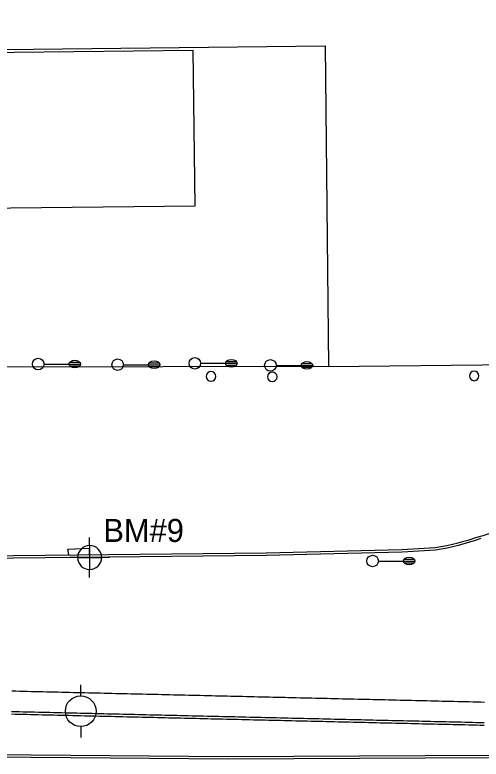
# Model space of a CAD drawing. Extents: x 2145380 to 2157287, y 139568 to 149130.
# Drawn here: x 2147980.9 to 2148102.2, y 143189.7 to 143383.4 of the extents above; entities that cross this region are included whole.
import ezdxf

# ---------------------------------------------------------------- set-up
doc = ezdxf.new("R2010")
doc.units = 0
for name, color, linetype in [('PR_PREVIOUSLY CONSTRUCTED', 7, 'Continuous'), ('SURV_Benchmark', 7, 'Continuous'), ('TOPO_Building', 7, 'Continuous'), ('TOPO_Curb Back', 7, 'Continuous'), ('TOPO_DRAIN_Inlet Grate', 7, 'Continuous'), ('TOPO_Fence', 7, 'Continuous'), ('TOPO_Light Pole', 7, 'Continuous'), ('TOPO_Misc', 7, 'Continuous'), ('TOPO_Misc Line', 7, 'Continuous'), ('TOPO_Power Pole', 7, 'Continuous')]:
    doc.layers.add(name, color=color, linetype=linetype)

# ---------------------------------------------------------------- blocks, each defined once
blk = doc.blocks.new('POST')
at = {"layer": 'TOPO_Misc'}
for start, end in [(90, 180), (180, 270), (360, 90), (270, 0)]:
    blk.add_arc((-0.01, 0.03), 3.16, start, end, dxfattribs=at)
blk = doc.blocks.new('LP')
at = {"layer": 'TOPO_Light Pole'}
blk.add_line((3.81, 0), (20.32, 0), dxfattribs=at)
for points in [[(20.32, 0), (27.94, 0)], [(20.32, 0), (23.5, 0)], [(20.83, 1.27), (27.43, 1.27)], [(20.83, 1.27), (23.5, 1.27)], [(23.71, 1.27), (27.43, 1.27)], [(23.71, 0), (27.94, 0)], [(20.83, -1.27), (27.43, -1.27)], [(20.83, -1.27), (23.5, -1.27)], [(23.71, -1.27), (27.43, -1.27)]]:
    blk.add_lwpolyline(points, dxfattribs=at)
blk.add_circle((0, 0), 3.81, dxfattribs=at)
blk.add_ellipse((24.13, 0), major_axis=(3.81, 0), ratio=0.666667, dxfattribs=at)
blk = doc.blocks.new('POWPOL')
at = {"layer": 'TOPO_Power Pole'}
for p, q in [((0, 10.16), (0, 17.34)), ((0, -10.16), (0, -17.34))]:
    blk.add_line(p, q, dxfattribs=at)
blk.add_circle((0, 0), 10.16, dxfattribs=at)
blk = doc.blocks.new('BM')
at = {"layer": 'SURV_Benchmark'}
for p, q in [((0, 2.49), (0, 4.15)), ((-2.49, 0), (-4.16, 0)), ((4.16, 0), (2.49, 0)), ((0, -4.16), (0, -2.49))]:
    blk.add_line(p, q, dxfattribs=at)
for points in [[(0, 2.49), (0, 2.49), (0, 0), (2.49, 0), (2.49, 0), (2.49, 0)], [(0, 2.49), (0, 2.49), (0, 0), (2.49, 0), (2.49, 0), (2.49, 0), (2.49, 0)], [(-2.5, 0), (-2.49, 0), (0, 0), (0, -2.49), (0, -2.49)], [(-2.5, 0), (-2.49, 0), (0, 0), (0, -2.49), (0, -2.49)]]:
    blk.add_lwpolyline(points, dxfattribs=at)
for start, end in [(90.0638, 180.0068), (0.0638, 90.0068), (0.0638, 90.0068), (180.0638, 270.0068), (180.0638, 270.0068), (269.9472, 359.9927)]:
    blk.add_arc((0, 0), 2.5, start, end, dxfattribs=at)

msp = doc.modelspace()

# ---------------------------------------------------------------- linework, layer by layer
at = {"layer": 'PR_PREVIOUSLY CONSTRUCTED'}
for points in [[(2147980.15, 143207.5), (2147981.15, 143207.48), (2147982.15, 143207.45), (2147983.15, 143207.43), (2147984.15, 143207.41), (2147985.15, 143207.38), (2147986.15, 143207.36), (2147987.15, 143207.34), (2147988.15, 143207.31), (2147989.15, 143207.29), (2147990.15, 143207.27), (2147991.15, 143207.24), (2147992.15, 143207.22), (2147993.15, 143207.19), (2147994.15, 143207.17), (2147995.15, 143207.15), (2147996.15, 143207.12), (2147997.15, 143207.1), (2147998.15, 143207.08), (2147999.15, 143207.05), (2148000.15, 143207.03), (2148001.15, 143207.01), (2148002.15, 143206.98), (2148003.15, 143206.96), (2148004.15, 143206.94), (2148005.15, 143206.91), (2148006.15, 143206.89), (2148007.15, 143206.86), (2148008.15, 143206.84), (2148009.15, 143206.82), (2148010.15, 143206.79), (2148011.15, 143206.77), (2148012.14, 143206.75), (2148013.14, 143206.72), (2148014.14, 143206.7), (2148015.14, 143206.68), (2148016.14, 143206.65), (2148017.14, 143206.63), (2148018.14, 143206.61), (2148019.14, 143206.58), (2148020.14, 143206.56), (2148021.14, 143206.54), (2148022.14, 143206.51), (2148023.14, 143206.49), (2148024.14, 143206.46), (2148025.14, 143206.44), (2148026.14, 143206.42), (2148027.14, 143206.39), (2148028.14, 143206.37), (2148029.14, 143206.35), (2148030.14, 143206.32), (2148031.14, 143206.3), (2148032.14, 143206.28), (2148033.14, 143206.25), (2148034.14, 143206.23), (2148035.14, 143206.2), (2148036.14, 143206.18), (2148037.14, 143206.16), (2148038.14, 143206.13), (2148039.14, 143206.11), (2148040.14, 143206.09), (2148041.14, 143206.06), (2148042.14, 143206.04), (2148043.14, 143206.02), (2148044.13, 143205.99), (2148045.13, 143205.97), (2148046.13, 143205.95), (2148047.13, 143205.92), (2148048.13, 143205.9), (2148049.13, 143205.88), (2148050.13, 143205.85), (2148051.13, 143205.83), (2148052.13, 143205.8), (2148053.13, 143205.78), (2148054.13, 143205.76), (2148055.13, 143205.73), (2148056.13, 143205.71), (2148057.13, 143205.69), (2148058.13, 143205.66), (2148059.13, 143205.64), (2148060.13, 143205.62), (2148061.13, 143205.59), (2148062.13, 143205.57), (2148063.13, 143205.55), (2148064.13, 143205.52), (2148065.13, 143205.5), (2148066.13, 143205.47), (2148067.13, 143205.45), (2148068.13, 143205.43), (2148069.13, 143205.4), (2148070.13, 143205.38), (2148071.13, 143205.36), (2148072.13, 143205.33), (2148073.13, 143205.31), (2148074.13, 143205.29), (2148075.13, 143205.26), (2148076.13, 143205.24), (2148077.13, 143205.22), (2148078.13, 143205.19), (2148079.13, 143205.17), (2148080.12, 143205.15), (2148081.12, 143205.12), (2148082.12, 143205.1), (2148083.12, 143205.07), (2148084.12, 143205.05), (2148085.12, 143205.03), (2148086.12, 143205), (2148087.12, 143204.98), (2148088.12, 143204.96), (2148089.12, 143204.93), (2148090.12, 143204.91), (2148091.12, 143204.89), (2148092.12, 143204.86), (2148093.12, 143204.84), (2148094.12, 143204.82), (2148095.12, 143204.79), (2148096.12, 143204.77), (2148097.12, 143204.74), (2148098.12, 143204.72), (2148099.12, 143204.7), (2148100.12, 143204.67), (2148101.12, 143204.65), (2148102.12, 143204.63), (2148103.12, 143204.6)], [(2147980.01, 143201.49), (2147981.01, 143201.47), (2147982.01, 143201.45), (2147983.01, 143201.42), (2147984.01, 143201.4), (2147985.01, 143201.38), (2147986.01, 143201.35), (2147987.01, 143201.33), (2147988.01, 143201.31), (2147989.01, 143201.28), (2147990.01, 143201.26), (2147991.01, 143201.24), (2147992.01, 143201.21), (2147993.01, 143201.19), (2147994.01, 143201.16), (2147995.01, 143201.14), (2147996.01, 143201.12), (2147997.01, 143201.09), (2147998.01, 143201.07), (2147999.01, 143201.05), (2148000.01, 143201.02), (2148001.01, 143201), (2148002.01, 143200.98), (2148003, 143200.95), (2148004, 143200.93), (2148005, 143200.91), (2148006, 143200.88), (2148007, 143200.86), (2148008, 143200.83), (2148009, 143200.81), (2148010, 143200.79), (2148011, 143200.77), (2148012, 143200.74), (2148013, 143200.72), (2148014, 143200.69), (2148015, 143200.67), (2148016, 143200.65), (2148017, 143200.62), (2148018, 143200.6), (2148019, 143200.58), (2148020, 143200.55), (2148021, 143200.53), (2148022, 143200.51), (2148023, 143200.48), (2148024, 143200.46), (2148025, 143200.43), (2148026, 143200.41), (2148027, 143200.39), (2148028, 143200.36), (2148029, 143200.34), (2148030, 143200.32), (2148031, 143200.29), (2148032, 143200.27), (2148033, 143200.25), (2148034, 143200.22), (2148035, 143200.2), (2148036, 143200.18), (2148037, 143200.15), (2148038, 143200.13), (2148038.99, 143200.1), (2148039.99, 143200.08), (2148040.99, 143200.06), (2148041.99, 143200.04), (2148042.99, 143200.01), (2148043.99, 143199.99), (2148044.99, 143199.96), (2148045.99, 143199.94), (2148046.99, 143199.92), (2148047.99, 143199.89), (2148048.99, 143199.87), (2148049.99, 143199.85), (2148050.99, 143199.82), (2148051.99, 143199.8), (2148052.99, 143199.78), (2148053.99, 143199.75), (2148054.99, 143199.73), (2148055.99, 143199.7), (2148056.99, 143199.68), (2148057.99, 143199.66), (2148058.99, 143199.63), (2148059.99, 143199.61), (2148060.99, 143199.59), (2148061.99, 143199.56), (2148062.99, 143199.54), (2148063.99, 143199.52), (2148064.99, 143199.49), (2148065.99, 143199.47), (2148066.99, 143199.45), (2148067.99, 143199.42), (2148068.99, 143199.4), (2148069.99, 143199.38), (2148070.99, 143199.35), (2148071.99, 143199.33), (2148072.99, 143199.3), (2148073.99, 143199.28), (2148074.98, 143199.26), (2148075.98, 143199.23), (2148076.98, 143199.21), (2148077.98, 143199.19), (2148078.98, 143199.16), (2148079.98, 143199.14), (2148080.98, 143199.12), (2148081.98, 143199.09), (2148082.98, 143199.07), (2148083.98, 143199.05), (2148084.98, 143199.02), (2148085.98, 143199), (2148086.98, 143198.97), (2148087.98, 143198.95), (2148088.98, 143198.93), (2148089.98, 143198.9), (2148090.98, 143198.88), (2148091.98, 143198.86), (2148092.98, 143198.83), (2148093.98, 143198.81), (2148094.98, 143198.79), (2148095.98, 143198.76), (2148096.98, 143198.74), (2148097.98, 143198.72), (2148098.98, 143198.69), (2148099.98, 143198.67), (2148100.98, 143198.64), (2148101.98, 143198.62), (2148102.98, 143198.6)], [(2147980.03, 143202.16), (2147981.03, 143202.14), (2147982.03, 143202.11), (2147983.03, 143202.09), (2147984.03, 143202.07), (2147985.03, 143202.04), (2147986.03, 143202.02), (2147987.02, 143202), (2147988.02, 143201.97), (2147989.02, 143201.95), (2147990.02, 143201.93), (2147991.02, 143201.9), (2147992.02, 143201.88), (2147993.02, 143201.86), (2147994.02, 143201.83), (2147995.02, 143201.81), (2147996.02, 143201.79), (2147997.02, 143201.76), (2147998.02, 143201.74), (2147999.02, 143201.71), (2148000.02, 143201.69), (2148001.02, 143201.67), (2148002.02, 143201.64), (2148003.02, 143201.62), (2148004.02, 143201.6), (2148005.02, 143201.57), (2148006.02, 143201.55), (2148007.02, 143201.53), (2148008.02, 143201.5), (2148009.02, 143201.48), (2148010.02, 143201.46), (2148011.02, 143201.43), (2148012.02, 143201.41), (2148013.02, 143201.38), (2148014.02, 143201.36), (2148015.02, 143201.34), (2148016.02, 143201.31), (2148017.02, 143201.29), (2148018.02, 143201.27), (2148019.02, 143201.24), (2148020.02, 143201.22), (2148021.02, 143201.2), (2148022.02, 143201.17), (2148023.01, 143201.15), (2148024.01, 143201.13), (2148025.01, 143201.1), (2148026.01, 143201.08), (2148027.01, 143201.05), (2148028.01, 143201.03), (2148029.01, 143201.01), (2148030.01, 143200.98), (2148031.01, 143200.96), (2148032.01, 143200.94), (2148033.01, 143200.91), (2148034.01, 143200.89), (2148035.01, 143200.87), (2148036.01, 143200.84), (2148037.01, 143200.82), (2148038.01, 143200.8), (2148039.01, 143200.77), (2148040.01, 143200.75), (2148041.01, 143200.73), (2148042.01, 143200.7), (2148043.01, 143200.68), (2148044.01, 143200.65), (2148045.01, 143200.63), (2148046.01, 143200.61), (2148047.01, 143200.58), (2148048.01, 143200.56), (2148049.01, 143200.54), (2148050.01, 143200.51), (2148051.01, 143200.49), (2148052.01, 143200.47), (2148053.01, 143200.44), (2148054.01, 143200.42), (2148055.01, 143200.4), (2148056.01, 143200.37), (2148057.01, 143200.35), (2148058.01, 143200.32), (2148059, 143200.3), (2148060, 143200.28), (2148061, 143200.26), (2148062, 143200.23), (2148063, 143200.21), (2148064, 143200.18), (2148065, 143200.16), (2148066, 143200.14), (2148067, 143200.11), (2148068, 143200.09), (2148069, 143200.07), (2148070, 143200.04), (2148071, 143200.02), (2148072, 143200), (2148073, 143199.97), (2148074, 143199.95), (2148075, 143199.92), (2148076, 143199.9), (2148077, 143199.88), (2148078, 143199.85), (2148079, 143199.83), (2148080, 143199.81), (2148081, 143199.78), (2148082, 143199.76), (2148083, 143199.74), (2148084, 143199.71), (2148085, 143199.69), (2148086, 143199.67), (2148087, 143199.64), (2148088, 143199.62), (2148089, 143199.6), (2148090, 143199.57), (2148091, 143199.55), (2148092, 143199.52), (2148093, 143199.5), (2148094, 143199.48), (2148094.99, 143199.45), (2148095.99, 143199.43), (2148096.99, 143199.41), (2148097.99, 143199.38), (2148098.99, 143199.36), (2148099.99, 143199.34), (2148100.99, 143199.31), (2148101.99, 143199.29), (2148102.99, 143199.27)]]:
    msp.add_lwpolyline(points, dxfattribs=at)
at = {"layer": 'TOPO_Building'}
msp.add_lwpolyline([(2147873.27, 143665.68), (2147875.33, 143479.79), (2147885.79, 143479.91), (2147886.96, 143373.39), (2148061.61, 143375.32), (2148062.53, 143291.91), (2148110.45, 143292.43), (2148108.62, 143458.32), (2148117.66, 143458.42), (2148117.71, 143453.92), (2148177.01, 143454.58), (2148176.97, 143458.5), (2148180.6, 143458.54), (2148178.28, 143668.45)], dxfattribs=at)
at = {"layer": 'TOPO_Curb Back'}
for points in [[(2147886.94, 143253.61), (2147887, 143250.5), (2147887.04, 143241.54), (2147964.05, 143241.93), (2148046.3, 143242.85), (2148081.65, 143243.66), (2148090.34, 143244.19)], [(2147887.54, 143253.61), (2147887.6, 143250.51), (2147887.64, 143242.14), (2147964.04, 143242.53), (2148046.29, 143243.45), (2148081.62, 143244.26), (2148090.27, 143244.79)], [(2148215.03, 143191.07), (2148189.03, 143190.98), (2148104.77, 143190.12), (2148036.43, 143189.75), (2147954.44, 143190.43), (2147894.97, 143191.9)], [(2148215.03, 143191.67), (2148189.03, 143191.58), (2148104.76, 143190.72), (2148036.43, 143190.35), (2147954.45, 143191.03), (2147894.98, 143192.5)]]:
    msp.add_lwpolyline(points, dxfattribs=at)
for centre, radius, start, end in [((2148092.52, 143283.64), 37.11, 284.8518, 304.0243), ((2148078.32, 143316.51), 72.71, 279.4567, 289.0321), ((2148078.32, 143316.52), 73.32, 279.433, 289.0148)]:
    msp.add_arc(centre, radius, start, end, dxfattribs=at)
at = {"layer": 'TOPO_DRAIN_Inlet Grate'}
msp.add_lwpolyline([(2147994.99, 143242.88), (2147994.67, 143244.39), (2148000.25, 143244.63), (2148000.27, 143242.94)], dxfattribs=at)
at = {"layer": 'TOPO_Fence'}
msp.add_line((2148062.53, 143291.91), (2147908.35, 143291.61), dxfattribs=at)
at = {"layer": 'TOPO_Misc Line'}
msp.add_lwpolyline([(2148027.34, 143374.15), (2147887.53, 143372.57), (2147888.45, 143291.38), (2147908.35, 143291.61), (2147907.89, 143332.41), (2148027.8, 143333.76)], close=True, dxfattribs=at)

# ---------------------------------------------------------------- block references
at = {"layer": 'SURV_Benchmark', "xscale": 1.25, "yscale": 1.25}
msp.add_blockref('BM', (2148000.37, 143242.2), dxfattribs=at)
at = {"layer": 'TOPO_Light Pole', "xscale": 0.39370000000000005, "yscale": 0.3937000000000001}
for p in [(2147986.99, 143292.55), (2148027.72, 143292.74), (2148007.65, 143292.39), (2148047.39, 143292.2), (2148073.98, 143241.3)]:
    msp.add_blockref('LP', p, dxfattribs=at)
at = {"layer": 'TOPO_Misc', "xscale": 0.39370000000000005, "yscale": 0.3937000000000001}
for p in [(2148031.93, 143289.33), (2148047.88, 143289.22), (2148100.41, 143289.45)]:
    msp.add_blockref('POST', p, dxfattribs=at)
at = {"layer": 'TOPO_Power Pole', "xscale": 0.39370000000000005, "yscale": 0.3937000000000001}
msp.add_blockref('POWPOL', (2147998.05, 143202.21), dxfattribs=at)

# ---------------------------------------------------------------- texts
at = {"layer": 'SURV_Benchmark'}
msp.add_text('BM#9', height=6, dxfattribs=at).set_placement((2148003.93, 143246.25))

doc.saveas('drawing.dxf')
